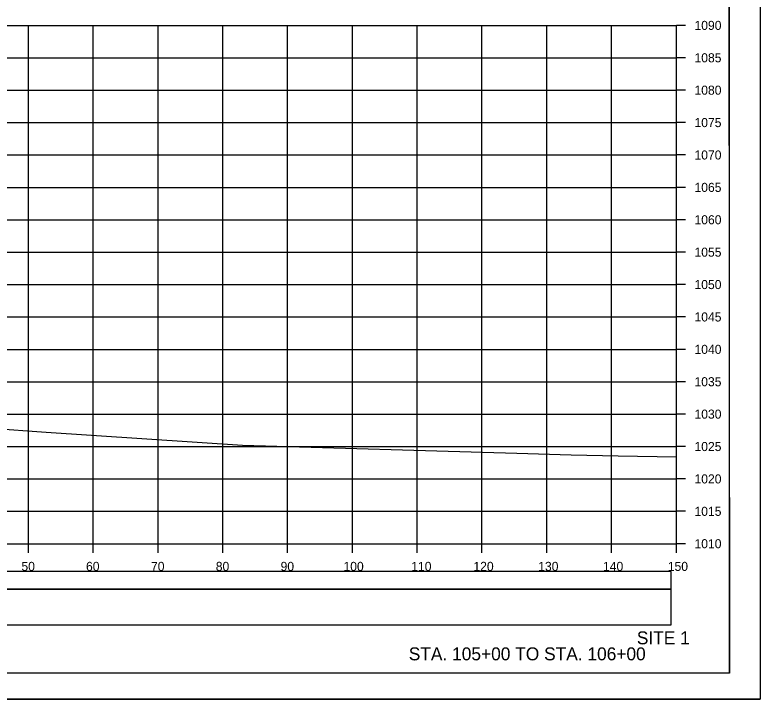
# Model space of a CAD drawing. Extents: x 1370565 to 1374448, y 301010 to 304637.
# Drawn here: x 1370782.9 to 1370898, y 301650.5 to 301756.1 of the extents above; entities that cross this region are included whole.
import ezdxf

# ---------------------------------------------------------------- set-up
doc = ezdxf.new("R2010")
doc.units = 0
for name, color, linetype in [('R_Axis', 7, 'Continuous'), ('R_Axis Annot', 7, 'Continuous'), ('R_Border', 7, 'Continuous'), ('R_Draft', 7, 'Continuous'), ('R_Drive', 7, 'Continuous'), ('R_Exist Surface', 7, 'Continuous'), ('R_Grid', 7, 'Continuous'), ('R_No Plot', 7, 'Continuous')]:
    doc.layers.add(name, color=color, linetype=linetype)

msp = doc.modelspace()

# ---------------------------------------------------------------- linework, layer by layer
at = {"layer": 'R_Axis'}
for p, q in [((1370885.03, 301674.49), (1370885.03, 301754.49)), ((1370886.43, 301754.49), (1370885.03, 301754.49)), ((1370886.43, 301749.49), (1370885.03, 301749.49)), ((1370886.43, 301744.49), (1370885.03, 301744.49)), ((1370886.43, 301739.49), (1370885.03, 301739.49)), ((1370886.43, 301734.49), (1370885.03, 301734.49)), ((1370886.43, 301729.49), (1370885.03, 301729.49)), ((1370886.43, 301724.49), (1370885.03, 301724.49)), ((1370886.43, 301719.49), (1370885.03, 301719.49)), ((1370886.43, 301714.49), (1370885.03, 301714.49)), ((1370886.43, 301709.49), (1370885.03, 301709.49)), ((1370886.43, 301704.49), (1370885.03, 301704.49)), ((1370886.43, 301699.49), (1370885.03, 301699.49)), ((1370886.43, 301694.49), (1370885.03, 301694.49)), ((1370886.43, 301689.49), (1370885.03, 301689.49)), ((1370886.43, 301684.49), (1370885.03, 301684.49)), ((1370886.43, 301679.49), (1370885.03, 301679.49)), ((1370585.03, 301674.49), (1370885.03, 301674.49)), ((1370785.03, 301673.09), (1370785.03, 301674.49)), ((1370795.03, 301673.09), (1370795.03, 301674.49)), ((1370805.03, 301673.09), (1370805.03, 301674.49)), ((1370815.03, 301673.09), (1370815.03, 301674.49)), ((1370825.03, 301673.09), (1370825.03, 301674.49)), ((1370835.03, 301673.09), (1370835.03, 301674.49)), ((1370845.03, 301673.09), (1370845.03, 301674.49)), ((1370855.03, 301673.09), (1370855.03, 301674.49)), ((1370865.03, 301673.09), (1370865.03, 301674.49)), ((1370875.03, 301673.09), (1370875.03, 301674.49)), ((1370885.03, 301673.09), (1370885.03, 301674.49)), ((1370886.43, 301674.49), (1370885.03, 301674.49))]:
    msp.add_line(p, q, dxfattribs=at)
at = {"layer": 'R_Border'}
for q in [(1370893.21, 301859.95), (1370577.03, 301654.49)]:
    msp.add_line((1370893.21, 301654.49), q, dxfattribs=at)
at = {"layer": 'R_Drive'}
for points in [[(1370585.82, 301667.47), (1370884.24, 301667.47), (1370884.24, 301670.18), (1370585.82, 301670.18)], [(1370585.82, 301661.95), (1370884.24, 301661.95), (1370884.24, 301667.47), (1370585.82, 301667.47)]]:
    msp.add_lwpolyline(points, close=True, dxfattribs=at)
at = {"layer": 'R_Exist Surface'}
msp.add_lwpolyline([(1370585.03, 301739.76), (1370654.67, 301719.57), (1370681.98, 301709.45), (1370696.18, 301704.03), (1370707.43, 301698.39), (1370712.28, 301695.91), (1370722.96, 301697.24), (1370724.92, 301697.5), (1370733.82, 301697.75), (1370735.07, 301697.79), (1370744.65, 301697.65), (1370745.32, 301697.64), (1370747.49, 301697.29), (1370779.11, 301692.32), (1370787.74, 301691.72), (1370818.07, 301689.7), (1370860.42, 301688.45), (1370868.77, 301688.21), (1370876.05, 301688.04), (1370885.03, 301687.88)], dxfattribs=at)
at = {"layer": 'R_Grid'}
for p, q in [((1370585.03, 301754.49), (1370885.03, 301754.49)), ((1370785.03, 301674.49), (1370785.03, 301754.49)), ((1370795.03, 301674.49), (1370795.03, 301754.49)), ((1370805.03, 301674.49), (1370805.03, 301754.49)), ((1370815.03, 301674.49), (1370815.03, 301754.49)), ((1370825.03, 301674.49), (1370825.03, 301754.49)), ((1370835.03, 301674.49), (1370835.03, 301754.49)), ((1370845.03, 301674.49), (1370845.03, 301754.49)), ((1370855.03, 301674.49), (1370855.03, 301754.49)), ((1370865.03, 301674.49), (1370865.03, 301754.49)), ((1370875.03, 301674.49), (1370875.03, 301754.49)), ((1370885.03, 301674.49), (1370885.03, 301754.49)), ((1370585.03, 301749.49), (1370885.03, 301749.49)), ((1370585.03, 301744.49), (1370885.03, 301744.49)), ((1370585.03, 301739.49), (1370885.03, 301739.49)), ((1370585.03, 301734.49), (1370885.03, 301734.49)), ((1370585.03, 301729.49), (1370885.03, 301729.49)), ((1370585.03, 301724.49), (1370885.03, 301724.49)), ((1370585.03, 301719.49), (1370885.03, 301719.49)), ((1370585.03, 301714.49), (1370885.03, 301714.49)), ((1370585.03, 301709.49), (1370885.03, 301709.49)), ((1370585.03, 301704.49), (1370885.03, 301704.49)), ((1370585.03, 301699.49), (1370885.03, 301699.49)), ((1370585.03, 301694.49), (1370885.03, 301694.49)), ((1370585.03, 301689.49), (1370885.03, 301689.49)), ((1370585.03, 301684.49), (1370885.03, 301684.49)), ((1370585.03, 301679.49), (1370885.03, 301679.49)), ((1370585.03, 301674.49), (1370885.03, 301674.49))]:
    msp.add_line(p, q, dxfattribs=at)
at = {"layer": 'R_No Plot'}
msp.add_line((1370564.63, 301650.51), (1370897.96, 301650.51), dxfattribs=at)
for points in [[(1370564.62, 301863.84), (1370897.96, 301863.84), (1370897.96, 301650.51), (1370564.62, 301650.51)], [(1370810.95, 301859.95), (1370830.57, 301859.95), (1370830.57, 301850.07), (1370846.68, 301850.07), (1370869.88, 301850.07), (1370869.88, 301817.4), (1370893.09, 301817.4), (1370893.21, 301654.49), (1370577.03, 301654.49), (1370577.03, 301859.95)]]:
    msp.add_lwpolyline(points, close=True, dxfattribs=at)

# ---------------------------------------------------------------- texts
at = {"layer": 'R_Axis Annot'}
for s, p in [('1090', (1370887.83, 301753.79)), ('1085', (1370887.83, 301748.79)), ('1080', (1370887.83, 301743.79)), ('1075', (1370887.83, 301738.79)), ('1070', (1370887.83, 301733.79)), ('1065', (1370887.83, 301728.79)), ('1060', (1370887.83, 301723.79)), ('1055', (1370887.83, 301718.79)), ('1050', (1370887.83, 301713.79)), ('1045', (1370887.83, 301708.79)), ('1040', (1370887.83, 301703.79)), ('1035', (1370887.83, 301698.79)), ('1030', (1370887.83, 301693.79)), ('1025', (1370887.83, 301688.79)), ('1020', (1370887.83, 301683.79)), ('1015', (1370887.83, 301678.79)), ('1010', (1370887.83, 301673.79)), ('50', (1370783.94, 301670.29)), ('60', (1370793.91, 301670.29)), ('70', (1370803.94, 301670.29)), ('80', (1370813.94, 301670.29)), ('90', (1370823.94, 301670.29)), ('100', (1370833.65, 301670.29)), ('110', (1370844.11, 301670.29)), ('120', (1370853.71, 301670.29)), ('130', (1370863.71, 301670.29)), ('140', (1370873.71, 301670.29)), ('150', (1370883.71, 301670.29))]:
    msp.add_text(s, height=1.4, dxfattribs=at).set_placement(p)
at = {"layer": 'R_Draft'}
for s, p in [('SITE 1', (1370878.93, 301658.96)), ('STA. 105+00 TO STA. 106+00', (1370843.73, 301656.49))]:
    msp.add_text(s, height=2, dxfattribs=at).set_placement(p)

doc.saveas('drawing.dxf')
